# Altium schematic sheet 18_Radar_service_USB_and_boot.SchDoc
size 289 x 396 mm
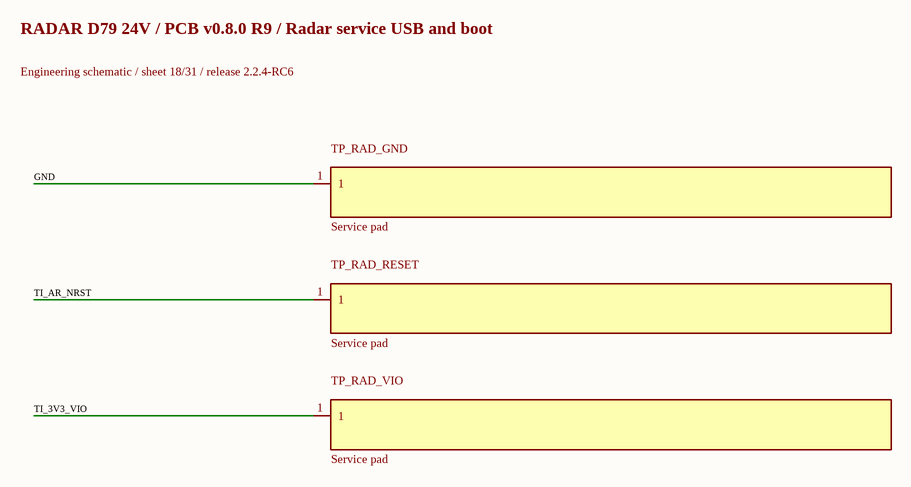
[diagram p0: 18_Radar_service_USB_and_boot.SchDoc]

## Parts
TP_RAD_GND  Service pad  [TestPoint_Pad_D1.5mm]
TP_RAD_RESET  Service pad  [TestPoint_Pad_D1.5mm]
TP_RAD_VIO  Service pad  [TestPoint_Pad_D1.5mm]

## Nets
GND: TP_RAD_GND.1
TI_3V3_VIO: TP_RAD_VIO.1
TI_AR_NRST: TP_RAD_RESET.1

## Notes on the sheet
- RADAR D79 24V / PCB v0.8.0 R9 / Radar service USB and boot
- Engineering schematic / sheet 18/31 / release 2.2.4-RC6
